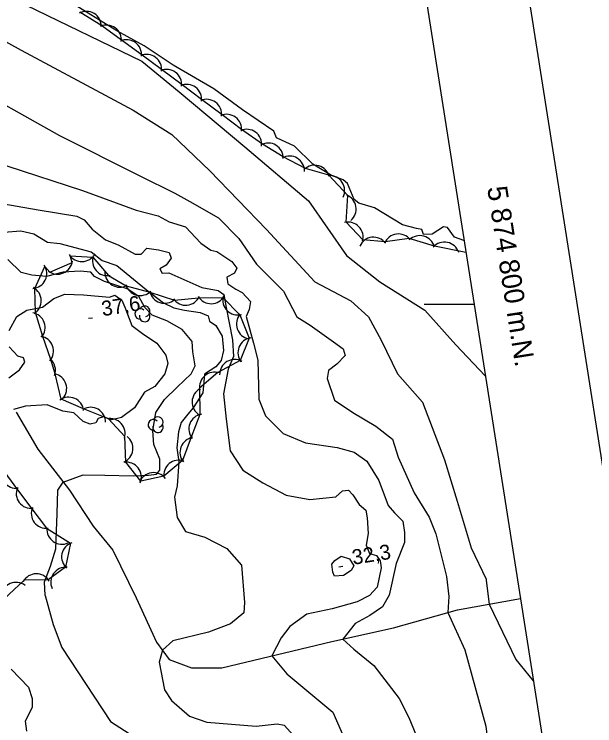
# Model space of a CAD drawing. Extents: x 646142 to 649934, y 5874075 to 5876351.
# Drawn here: x 649266.3 to 649382.6, y 5874715.6 to 5874858.2 of the extents above; entities that cross this region are included whole.
import ezdxf

# ---------------------------------------------------------------- set-up
doc = ezdxf.new("R2010")
doc.units = 0
for name, color, linetype in [('Niveau 1', 7, 'Continuous'), ('Niveau 2', 7, 'Continuous'), ('Niveau 3', 7, 'Continuous'), ('Niveau 4', 7, 'Continuous'), ('Niveau 44', 7, 'Continuous'), ('Niveau 60', 7, 'Continuous'), ('Niveau 61', 7, 'Continuous')]:
    doc.layers.add(name, color=color, linetype=linetype)

msp = doc.modelspace()

# ---------------------------------------------------------------- linework, layer by layer
at = {"layer": 'Niveau 1'}
for points in [[(649262.67, 5874820.43), (649271.14, 5874818.99), (649278.85, 5874817.73), (649280.32, 5874816.97), (649281.94, 5874815.08), (649284.62, 5874812.97), (649287.16, 5874811.99), (649290.51, 5874810.08), (649291.77, 5874810.11), (649292.89, 5874811.28), (649295.23, 5874810.98), (649297.37, 5874810.42), (649297.74, 5874809.31), (649296.76, 5874807.92), (649295.47, 5874807.19), (649295.92, 5874806.32), (649297.3, 5874806.36), (649303.88, 5874803.44), (649307.18, 5874802.79), (649308.32, 5874801.99), (649308.76, 5874799.39), (649310.02, 5874792.94), (649310.2, 5874789.61), (649309.14, 5874787.05), (649308.26, 5874782.09), (649308.77, 5874777.05), (649309.57, 5874770.66), (649312.12, 5874766.8), (649316.12, 5874764.26), (649320.8, 5874761.81), (649325.51, 5874760.97), (649330.74, 5874761.48), (649332.09, 5874762.68), (649333.23, 5874762.81), (649334.15, 5874761.88), (649335.42, 5874759.95), (649335.42, 5874759.95), (649336.71, 5874758.83), (649337.03, 5874757.24), (649337.18, 5874754.14), (649336.79, 5874751.77), (649337.45, 5874750.12), (649338.89, 5874749.71), (649339.6, 5874748.63), (649339.77, 5874747.27), (649338.99, 5874743.35), (649337.47, 5874741.67), (649334.97, 5874740.44), (649329.97, 5874739.04), (649324.92, 5874737.98)], [(649324.92, 5874737.98), (649321.54, 5874735.49), (649319.75, 5874733.2), (649317.92, 5874729.62), (649320.9, 5874726.03), (649330.15, 5874718.32), (649332.73, 5874712.38)]]:
    msp.add_lwpolyline(points, dxfattribs=at)
at = {"layer": 'Niveau 2'}
for points in [[(649049.16, 5874893.62), (649079, 5874896.65), (649090.19, 5874896.32), (649116.52, 5874895.68), (649132.02, 5874896.09), (649145.75, 5874897.7), (649157.56, 5874896.06), (649174.3, 5874893.83), (649186.57, 5874894.1), (649196.79, 5874893.9), (649208.02, 5874891.26), (649220.41, 5874886.66), (649245.94, 5874873.36), (649268.69, 5874859.98), (649291.86, 5874848.74), (649299.34, 5874842.64), (649312.52, 5874831.62), (649325.22, 5874820.78), (649332.84, 5874809.81), (649339.52, 5874804.54), (649348.56, 5874798.86), (649354.76, 5874791.91), (649360.65, 5874785.74)], [(649250.05, 5874860.73), (649267.69, 5874850.95), (649290.12, 5874838.95), (649297.9, 5874834.05), (649305.51, 5874826.81), (649316.81, 5874815.01), (649326.55, 5874804.54), (649333.73, 5874800.74), (649337.25, 5874797.55), (649339.8, 5874792.85), (649343.06, 5874786.15), (649348.05, 5874780.46), (649352.5, 5874768.89), (649355.04, 5874760.59), (649357.82, 5874751.26), (649360.8, 5874744.99), (649360.83, 5874744.72)], [(649255.36, 5874845.07), (649275.36, 5874833.85), (649291.49, 5874825.77), (649298.5, 5874822.3), (649301.48, 5874820.68), (649307.2, 5874817.41), (649311.29, 5874813.25), (649314.82, 5874808.1), (649320.23, 5874802.7), (649322.94, 5874797.56), (649325.58, 5874795.9), (649330.27, 5874792.51), (649332.18, 5874791.11), (649332.57, 5874789.76), (649330.94, 5874788.06), (649329.25, 5874786.82), (649328.99, 5874785.16), (649330.46, 5874780.81), (649334.11, 5874778.34), (649338.72, 5874775.63), (649342.05, 5874773.01), (649343.19, 5874769.43), (649346.39, 5874762.26), (649349.42, 5874757.39)], [(649264.85, 5874827.79), (649279.99, 5874822.85), (649290.75, 5874818.9), (649295.15, 5874817.8), (649297.38, 5874816.56), (649300.62, 5874815.55), (649303.67, 5874812.32), (649305.69, 5874810.93), (649306.88, 5874810.61), (649309.9, 5874808.65), (649310.88, 5874807.26), (649310.42, 5874806.27), (649308.9, 5874805.52), (649309.07, 5874804.15), (649310.7, 5874803.06), (649311.94, 5874802.4), (649313.66, 5874800.63), (649313.4, 5874798.98), (649312.76, 5874797.63), (649314.24, 5874792.24), (649315.12, 5874788.87), (649315.29, 5874781.01), (649316.63, 5874777.69), (649320.18, 5874774.16), (649324.68, 5874772.26), (649331.02, 5874771.39), (649334.37, 5874770.39), (649336.9, 5874768.61), (649339.34, 5874764.72), (649341.23, 5874759.73), (649342.45, 5874758.25), (649344.16, 5874756.6), (649344.44, 5874754.31), (649344.46, 5874752.34), (649342.8, 5874748.09), (649341.39, 5874741.78), (649340.07, 5874739.42), (649337.52, 5874737.72), (649334.6, 5874736.1), (649332.11, 5874732.97)], [(649264.22, 5874814.48), (649267.64, 5874814.77), (649270.25, 5874814.15), (649272.98, 5874812.51), (649275.43, 5874812.22), (649281.73, 5874810.54), (649283.9, 5874808.83), (649286.9, 5874807.8)], [(649272.49, 5874741.71), (649272.38, 5874744.46), (649273.6, 5874747.61), (649274.66, 5874751.08), (649274.93, 5874758.16), (649275.05, 5874762.79), (649276.11, 5874764.42), (649280.12, 5874765.9), (649284.49, 5874765.84), (649290.14, 5874765.7), (649293.22, 5874765.84), (649294.8, 5874766.02), (649295.51, 5874766.8), (649295.47, 5874768.99), (649294.3, 5874771.96), (649294.07, 5874774.71), (649294.65, 5874778.35), (649296.39, 5874780.98), (649298.95, 5874783.48), (649301.72, 5874786.11), (649302.56, 5874787.71), (649302.09, 5874790.54), (649301.95, 5874792.6), (649299.93, 5874795.01), (649296.85, 5874796.72), (649293.95, 5874797.88), (649292.49, 5874799.44), (649291.3, 5874801.61), (649288.93, 5874803.17), (649284.39, 5874804.6), (649282.42, 5874805.63), (649281.63, 5874806.46), (649279.54, 5874806.68), (649276.12, 5874806.51), (649272.78, 5874805.65), (649269.88, 5874805.89), (649267.74, 5874806.44), (649265.01, 5874809)], [(649286.9, 5874807.8), (649292.79, 5874802.95), (649296.22, 5874800.35), (649298.3, 5874799.32), (649300.43, 5874798.88), (649303.58, 5874798.44), (649305.17, 5874797.71), (649305.41, 5874796.7), (649306.67, 5874795.81), (649307.97, 5874793.65), (649308.21, 5874790.79), (649307.78, 5874788.77), (649306.67, 5874787.49), (649304.43, 5874786.07), (649304.09, 5874782.33), (649302.17, 5874779.33), (649301.06, 5874778.04), (649299.77, 5874776.39), (649299.21, 5874774.47), (649298.91, 5874771.32), (649299.26, 5874768.47), (649298.93, 5874763.69), (649298.41, 5874761.43)], [(649265.34, 5874794.77), (649266.83, 5874797.6), (649268.85, 5874798.87), (649271.98, 5874799.47), (649274.28, 5874801.24), (649276.47, 5874802.08), (649280.16, 5874801.93), (649285.37, 5874801.51), (649286.47, 5874801.87), (649287.85, 5874800.88)], [(649287.85, 5874800.88), (649288.49, 5874799.46), (649289.86, 5874795.82), (649292, 5874794.23), (649294.88, 5874792.27), (649296.68, 5874789.83), (649297.11, 5874788.16), (649296.45, 5874786.12), (649294.47, 5874783.58), (649292.44, 5874782.42), (649290.42, 5874779.3), (649287.79, 5874777.38), (649285.9, 5874776.93), (649284.22, 5874777.53), (649283.12, 5874777.17), (649282.65, 5874776.31), (649281.54, 5874776.06), (649280.1, 5874776.58), (649278.27, 5874778.33), (649276.06, 5874778.64), (649272.92, 5874779.89), (649268.6, 5874779.61), (649266.16, 5874778.97)], [(649265.25, 5874785.32), (649267.35, 5874786.95), (649268.42, 5874788.45), (649268.19, 5874789.35), (649267.01, 5874789.67), (649265.28, 5874791.54)], [(649298.41, 5874761.43), (649298.92, 5874757.33), (649300.65, 5874754.53), (649304.47, 5874753.36), (649308.89, 5874751.11), (649311.84, 5874747.76), (649312.42, 5874740.31), (649312.33, 5874738.22), (649309.61, 5874736.05), (649305.22, 5874734.37), (649298.08, 5874732.6), (649295.98, 5874730.74), (649295.35, 5874728.35), (649296.39, 5874722.81), (649297.8, 5874720.66), (649301.42, 5874717.5), (649304.9, 5874716.3), (649314.78, 5874715.5), (649318.97, 5874716), (649320.39, 5874715.71), (649322.26, 5874713.62)], [(649349.42, 5874757.39), (649350.76, 5874754.07), (649352.87, 5874745.49), (649353.37, 5874741.49), (649353.18, 5874738.3), (649356.54, 5874730.8), (649360.76, 5874715.5), (649361.9, 5874706.34), (649361.36, 5874701.39), (649359.89, 5874695.52), (649357.21, 5874689.28), (649356.76, 5874687.35), (649359.98, 5874680.06), (649365.28, 5874674.64), (649373.16, 5874671.63), (649376.71, 5874671), (649378.65, 5874671.33)], [(649331.8, 5874749.57), (649333.47, 5874749.07), (649334.34, 5874747.67), (649333.77, 5874746.68), (649332.28, 5874745.7), (649330.46, 5874745.59), (649330.13, 5874746.36), (649329.93, 5874747.96), (649330.53, 5874748.72), (649331.8, 5874749.57)], [(649360.83, 5874744.72), (649361.42, 5874739.97), (649366.74, 5874728.85), (649370.27, 5874724.57)], [(649272.49, 5874741.71), (649274.13, 5874735.89), (649275.86, 5874731.25), (649285.62, 5874716.47), (649292.11, 5874712.27), (649301.06, 5874706.86), (649303.29, 5874703.66), (649305.47, 5874699.07), (649305.23, 5874695.46), (649303.83, 5874689.17), (649297.63, 5874679.51), (649295.83, 5874675.48), (649293.93, 5874668.55)], [(649332.11, 5874732.97), (649334.33, 5874730.92), (649338.31, 5874727.68), (649343.4, 5874721.09), (649345.37, 5874717.26), (649347.36, 5874712.39), (649347.98, 5874706.55), (649346.87, 5874694.11), (649345.61, 5874683.07), (649347.29, 5874677.93), (649350.7, 5874673.69), (649354.13, 5874670.27), (649359.17, 5874665.88), (649364.43, 5874662.56), (649369.95, 5874659.96), (649378.84, 5874656.15), (649381.09, 5874655.81)], [(649265.73, 5874726.93), (649269.16, 5874723.3), (649269.89, 5874721.08), (649269.89, 5874719.24), (649268.51, 5874716.54), (649268.76, 5874714.49)]]:
    msp.add_lwpolyline(points, dxfattribs=at)
at = {"layer": 'Niveau 3'}
for p, q in [((649281.18, 5874797.25), (649281.97, 5874797.37)), ((649331.34, 5874747.44), (649332.13, 5874747.56))]:
    msp.add_line(p, q, dxfattribs=at)
at = {"layer": 'Niveau 4'}
for points in [[(649356.38, 5874812.87), (649354.49, 5874813.49), (649353.09, 5874815.43), (649352.26, 5874815.56), (649350.01, 5874814.13), (649348.28, 5874814.04), (649347.92, 5874815.05), (649346.85, 5874815.27), (649344.09, 5874816), (649338.45, 5874819.41), (649335.32, 5874820.33), (649334.42, 5874821.04), (649333.09, 5874824.26), (649332.19, 5874824.97), (649329.88, 5874825.86), (649326.12, 5874828.1), (649322.42, 5874831.74), (649318.85, 5874833.42), (649318.33, 5874834.76), (649312, 5874839.02), (649306.26, 5874843.24), (649298.13, 5874848), (649292.31, 5874851.86), (649286.84, 5874854.83), (649281.68, 5874858.07), (649273.63, 5874863.06)], [(649266.69, 5874778.46), (649271.06, 5874771.03), (649277.36, 5874762.78), (649282.16, 5874755.61), (649286.09, 5874750.76), (649290.72, 5874741.25), (649294.81, 5874732.37), (649297.32, 5874728.85), (649301.79, 5874727.18), (649307.88, 5874727.21), (649329.9, 5874732.48), (649342.24, 5874735.22), (649355.07, 5874738.83), (649367.67, 5874741.08)]]:
    msp.add_lwpolyline(points, dxfattribs=at)
at = {"layer": 'Niveau 44'}
for points in [[(649356.76, 5874810.45), (649350.45, 5874811.72), (649345.43, 5874813.24), (649340.62, 5874812.57), (649336.14, 5874812.98), (649332.79, 5874816.49), (649333.13, 5874821.84), (649329.31, 5874825.93), (649324.65, 5874827.29), (649320.16, 5874829.61), (649316.01, 5874832.12), (649311.85, 5874835.09), (649307.96, 5874838), (649303.84, 5874841.09), (649299.96, 5874844), (649295.84, 5874847.09), (649291.96, 5874850), (649287.78, 5874853.01), (649283.86, 5874855.86), (649279.47, 5874858.59)], [(649277.94, 5874808.42), (649277.49, 5874809.79), (649282.06, 5874809.49), (649285.21, 5874805.8), (649288.75, 5874803.72), (649293.45, 5874802.49), (649298.41, 5874800.87), (649303.24, 5874801.34), (649308.11, 5874801.39), (649311.53, 5874797.94), (649313.39, 5874793.25), (649311.57, 5874788.76), (649307.12, 5874786.39), (649303.44, 5874783.23), (649303.5, 5874777.96), (649301.78, 5874773.42), (649300, 5874768.74), (649296.28, 5874765.62), (649291.67, 5874764.59), (649288.67, 5874768.4), (649288.47, 5874773.53), (649285.22, 5874777.13), (649280.16, 5874779.09), (649275.71, 5874781.02), (649274.49, 5874786.11), (649273.68, 5874789), (649272.03, 5874793.57), (649270.58, 5874798.38), (649270.44, 5874803.23), (649272.48, 5874807.63), (649273.47, 5874806.52), (649277.94, 5874808.42)], [(649263.91, 5874767.07), (649266.79, 5874763.16), (649269.86, 5874759.04), (649272.79, 5874755.16), (649277.59, 5874752.16), (649276.59, 5874747.41), (649273.15, 5874744.85), (649268.29, 5874744.77), (649264.26, 5874740.97)]]:
    msp.add_lwpolyline(points, dxfattribs=at)
for centre, radius, start, end in [((649280.77, 5874855.75), 3, 359.0167, 118.9946), ((649284.78, 5874853.01), 3, 353.936, 113.914), ((649288.82, 5874850.07), 3, 353.936, 113.914), ((649292.84, 5874847.13), 3, 353.162, 113.14), ((649296.84, 5874844.13), 3, 353.162, 113.14), ((649300.85, 5874841.13), 3, 353.162, 113.14), ((649304.85, 5874838.13), 3, 353.162, 113.14), ((649308.85, 5874835.13), 3, 353.162, 113.14), ((649312.85, 5874832.13), 3, 353.162, 113.14), ((649317.18, 5874829.36), 3, 358.7907, 118.7687), ((649321.45, 5874826.76), 3, 358.7907, 118.7687), ((649326.48, 5874824.92), 3, 13.7468, 133.7247), ((649329.49, 5874822.85), 3, 333.0461, 93.0241), ((649331.8, 5874819.15), 3, 309.6477, 69.6256), ((649333.19, 5874813.52), 3, 343.6944, 103.6724), ((649343.27, 5874811.16), 3, 37.8759, 157.8538), ((649338.28, 5874810.5), 3, 36.7455, 156.7235), ((649347.54, 5874810.81), 3, 14.5142, 134.4921), ((649352.48, 5874809.51), 3, 18.5788, 138.5568), ((649279.88, 5874811.61), 3, 211.2765, 331.2545), ((649284.98, 5874808.79), 3, 160.5372, 280.5151), ((649275.01, 5874809.09), 3, 232.9663, 352.9443), ((649269.84, 5874806.22), 3, 274.1065, 34.0844), ((649287.48, 5874806.47), 3, 178.6494, 298.6274), ((649291.55, 5874804.81), 3, 195.3487, 315.3266), ((649268.74, 5874800.76), 3, 301.6265, 61.6045), ((649296.4, 5874803.26), 3, 191.8466, 311.8245), ((649300.66, 5874802.86), 3, 215.4955, 335.4734), ((649305.75, 5874803.17), 3, 211.2805, 331.2584), ((649311.07, 5874800.91), 3, 164.8132, 284.7912), ((649292.45, 5874798.66), 1.05, 282.2692, 149.7263), ((649269.5, 5874795.39), 3, 319.8009, 79.7789), ((649291.55, 5874798.13), 1.05, 44.1154, 269.804), ((649292.45, 5874797.61), 1.05, 166.9369, 29.6212), ((649313.82, 5874796.09), 3, 138.9744, 258.9523), ((649271.19, 5874790.69), 3, 319.8009, 79.7789), ((649314.11, 5874790.34), 3, 97.9742, 217.9521), ((649271.58, 5874786.86), 3, 339.5687, 49.2606), ((649310.45, 5874785.99), 3, 60.9015, 180.8794), ((649273.83, 5874783.17), 3, 318.3313, 78.3092), ((649306.43, 5874783.47), 3, 70.7075, 190.6854), ((649304.93, 5874780.47), 3, 118.5647, 238.5426), ((649277.24, 5874778.44), 3, 6.5313, 126.5093), ((649281.61, 5874776.42), 3, 359.6373, 119.6153), ((649285.54, 5874774.15), 3, 342.1438, 102.1217), ((649294.19, 5874775.91), 1.05, 44.1154, 269.804), ((649295.09, 5874776.44), 1.05, 282.2692, 149.7263), ((649304.29, 5874775.06), 3, 99.2725, 219.2505), ((649295.09, 5874775.39), 1.05, 166.9369, 29.6212), ((649287.1, 5874771.2), 3, 292.5342, 52.5121), ((649302.51, 5874770.39), 3, 99.2725, 219.2505), ((649288.78, 5874765.41), 3, 338.176, 98.154), ((649299.27, 5874765.83), 3, 70.0455, 190.0234), ((649266.77, 5874766.16), 3, 156.3503, 276.3283), ((649294.23, 5874763.32), 3, 38.172, 158.1499), ((649269.72, 5874762.15), 3, 157.0117, 276.9896), ((649272.73, 5874758.16), 3, 157.0117, 276.9896), ((649275.88, 5874754.96), 3, 174.4805, 294.4585), ((649278.81, 5874749.42), 3, 108.1368, 228.1147), ((649276.63, 5874744.37), 3, 84.9793, 204.9572), ((649270.75, 5874743.05), 3, 31.0345, 151.0125), ((649266.68, 5874741.33), 3, 53.0007, 172.9786)]:
    msp.add_arc(centre, radius, start, end, dxfattribs=at)
at = {"layer": 'Niveau 60'}
msp.add_line((649358.4, 5874800), (649348.4, 5874800), dxfattribs=at)
msp.add_lwpolyline([(649415.27, 5874569.37), (649908.85, 5874647.01), (649644.82, 5876326.04), (649151.17, 5876248.41), (649415.27, 5874569.37)], dxfattribs=at)
msp.add_lwpolyline([(646167.42, 5875779.32), (649130.97, 5876245.57), (649395.18, 5874566.24), (646431.63, 5874099.99)], close=True, dxfattribs=at)
msp.add_lwpolyline([(646167.42, 5875779.32), (649130.97, 5876245.57), (649395.18, 5874566.24), (646431.63, 5874099.99)], close=True, dxfattribs=at)

# ---------------------------------------------------------------- texts
at = {"layer": 'Niveau 3'}
for s, p in [('37,6 ', (649284.03, 5874797.66)), ('32,3 ', (649334.2, 5874747.85))]:
    msp.add_text(s, height=3, rotation=8.9405, dxfattribs=at).set_placement(p)
at = {"layer": 'Niveau 61'}
msp.add_text('5 874 800 m.N.', height=4, rotation=278.9411, dxfattribs=at).set_placement((649361.01, 5874823.44))

doc.saveas('drawing.dxf')
